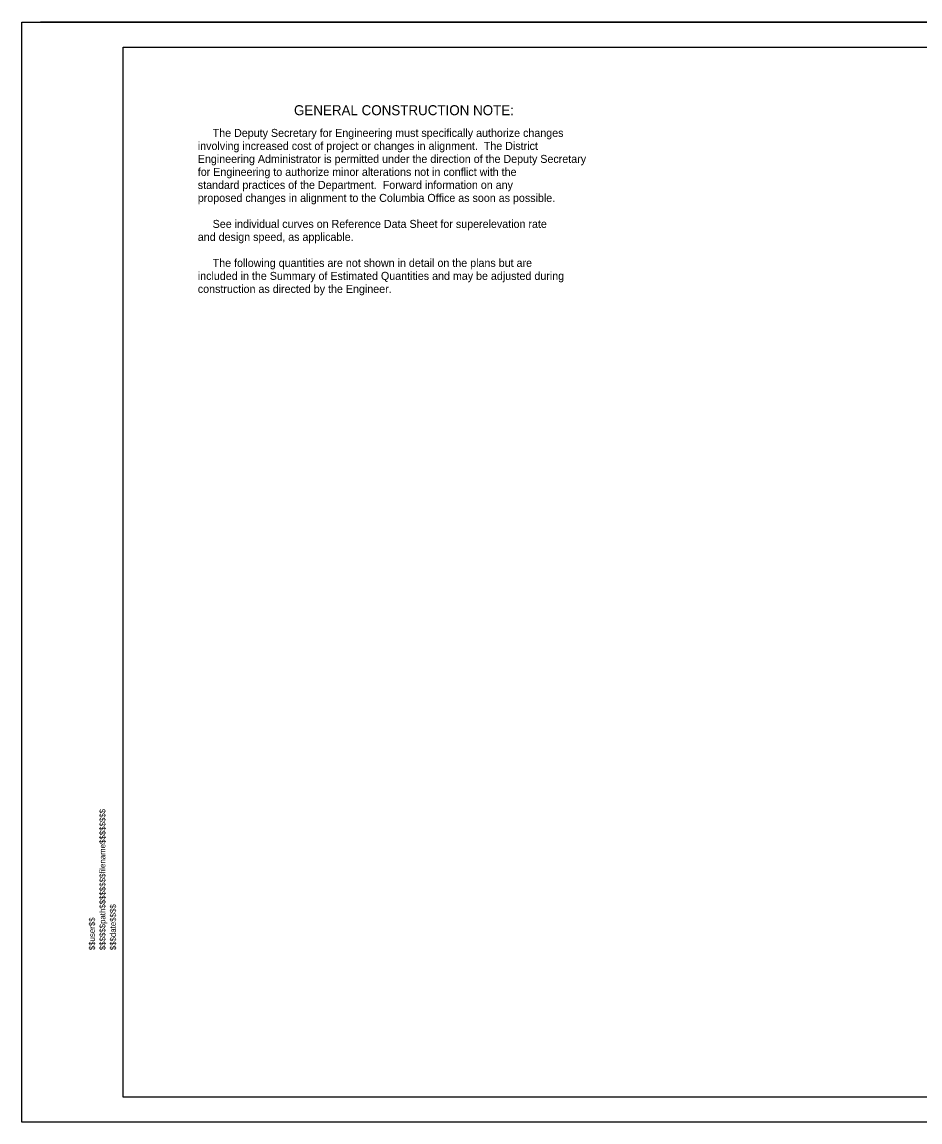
# Model space of a CAD drawing. Extents: x 8134 to 11793, y 3225 to 13425.
# Drawn here: x 9981 to 10879, y 5500 to 6600 of the extents above; entities that cross this region are included whole.
import ezdxf

# ---------------------------------------------------------------- set-up
doc = ezdxf.new("R2010")
doc.units = 0
for name, color, linetype in [('RD_SHT_Bndy', 7, 'Continuous'), ('RD_SHT_ID', 7, 'Continuous'), ('RD_SHT_IplotShp', 7, 'Continuous'), ('RD_TX_Qty', 7, 'Continuous')]:
    doc.layers.add(name, color=color, linetype=linetype)

msp = doc.modelspace()

# ---------------------------------------------------------------- linework, layer by layer
at = {"layer": 'RD_SHT_Bndy'}
for p, q in [((10000, 6600), (11760, 6600)), ((11760, 6600), (10000, 6600)), ((11760, 5500), (10000, 5500)), ((11760, 5500), (10000, 5500))]:
    msp.add_line(p, q, dxfattribs=at)
msp.add_lwpolyline([(10082.6, 6575), (11757.6, 6575), (11757.6, 5525), (10082.6, 5525)], close=True, dxfattribs=at)
at = {"layer": 'RD_SHT_IplotShp'}
msp.add_lwpolyline([(9981.4, 6600), (11777.4, 6600), (11777.4, 5500), (9981.4, 5500)], close=True, dxfattribs=at)

# ---------------------------------------------------------------- texts
at = {"layer": 'RD_SHT_ID'}
for s, p in [('$$$$$$path$$$$$$$$filename$$$$$$$$', (10064.8, 5671.8)), ('$$$date$$$$', (10075.3, 5671.8)), ('$$user$$', (10054.3, 5671.8))]:
    msp.add_text(s, height=5.88, rotation=90, dxfattribs=at).set_placement(p)
at = {"layer": 'RD_TX_Qty'}
for s, height, p in [('GENERAL CONSTRUCTION NOTE:', 10, (10253.4, 6506.8)), ('     The Deputy Secretary for Engineering must specifically authorize changes', 8, (10157.2, 6485.1)), ('involving increased cost of project or changes in alignment.  The District', 8, (10157.2, 6472.1)), ('Engineering Administrator is permitted under the direction of the Deputy Secretary', 8, (10157.2, 6459.1)), ('for Engineering to authorize minor alterations not in conflict with the', 8, (10157.2, 6446.1)), ('standard practices of the Department.  Forward information on any', 8, (10157.2, 6433.1)), ('proposed changes in alignment to the Columbia Office as soon as possible.', 8, (10157.2, 6420.1)), ('     See individual curves on Reference Data Sheet for superelevation rate', 8, (10157.2, 6394.1)), ('and design speed, as applicable.', 8, (10157.2, 6381.1)), ('     The following quantities are not shown in detail on the plans but are', 8, (10157.2, 6355.1)), ('included in the Summary of Estimated Quantities and may be adjusted during', 8, (10157.2, 6342.1)), ('construction as directed by the Engineer.', 8, (10157.2, 6329.1))]:
    msp.add_text(s, height=height, dxfattribs=at).set_placement(p)

doc.saveas('drawing.dxf')
